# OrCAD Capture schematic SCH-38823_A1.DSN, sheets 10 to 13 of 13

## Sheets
10 Page10 WIFI&Bluetooth: size B
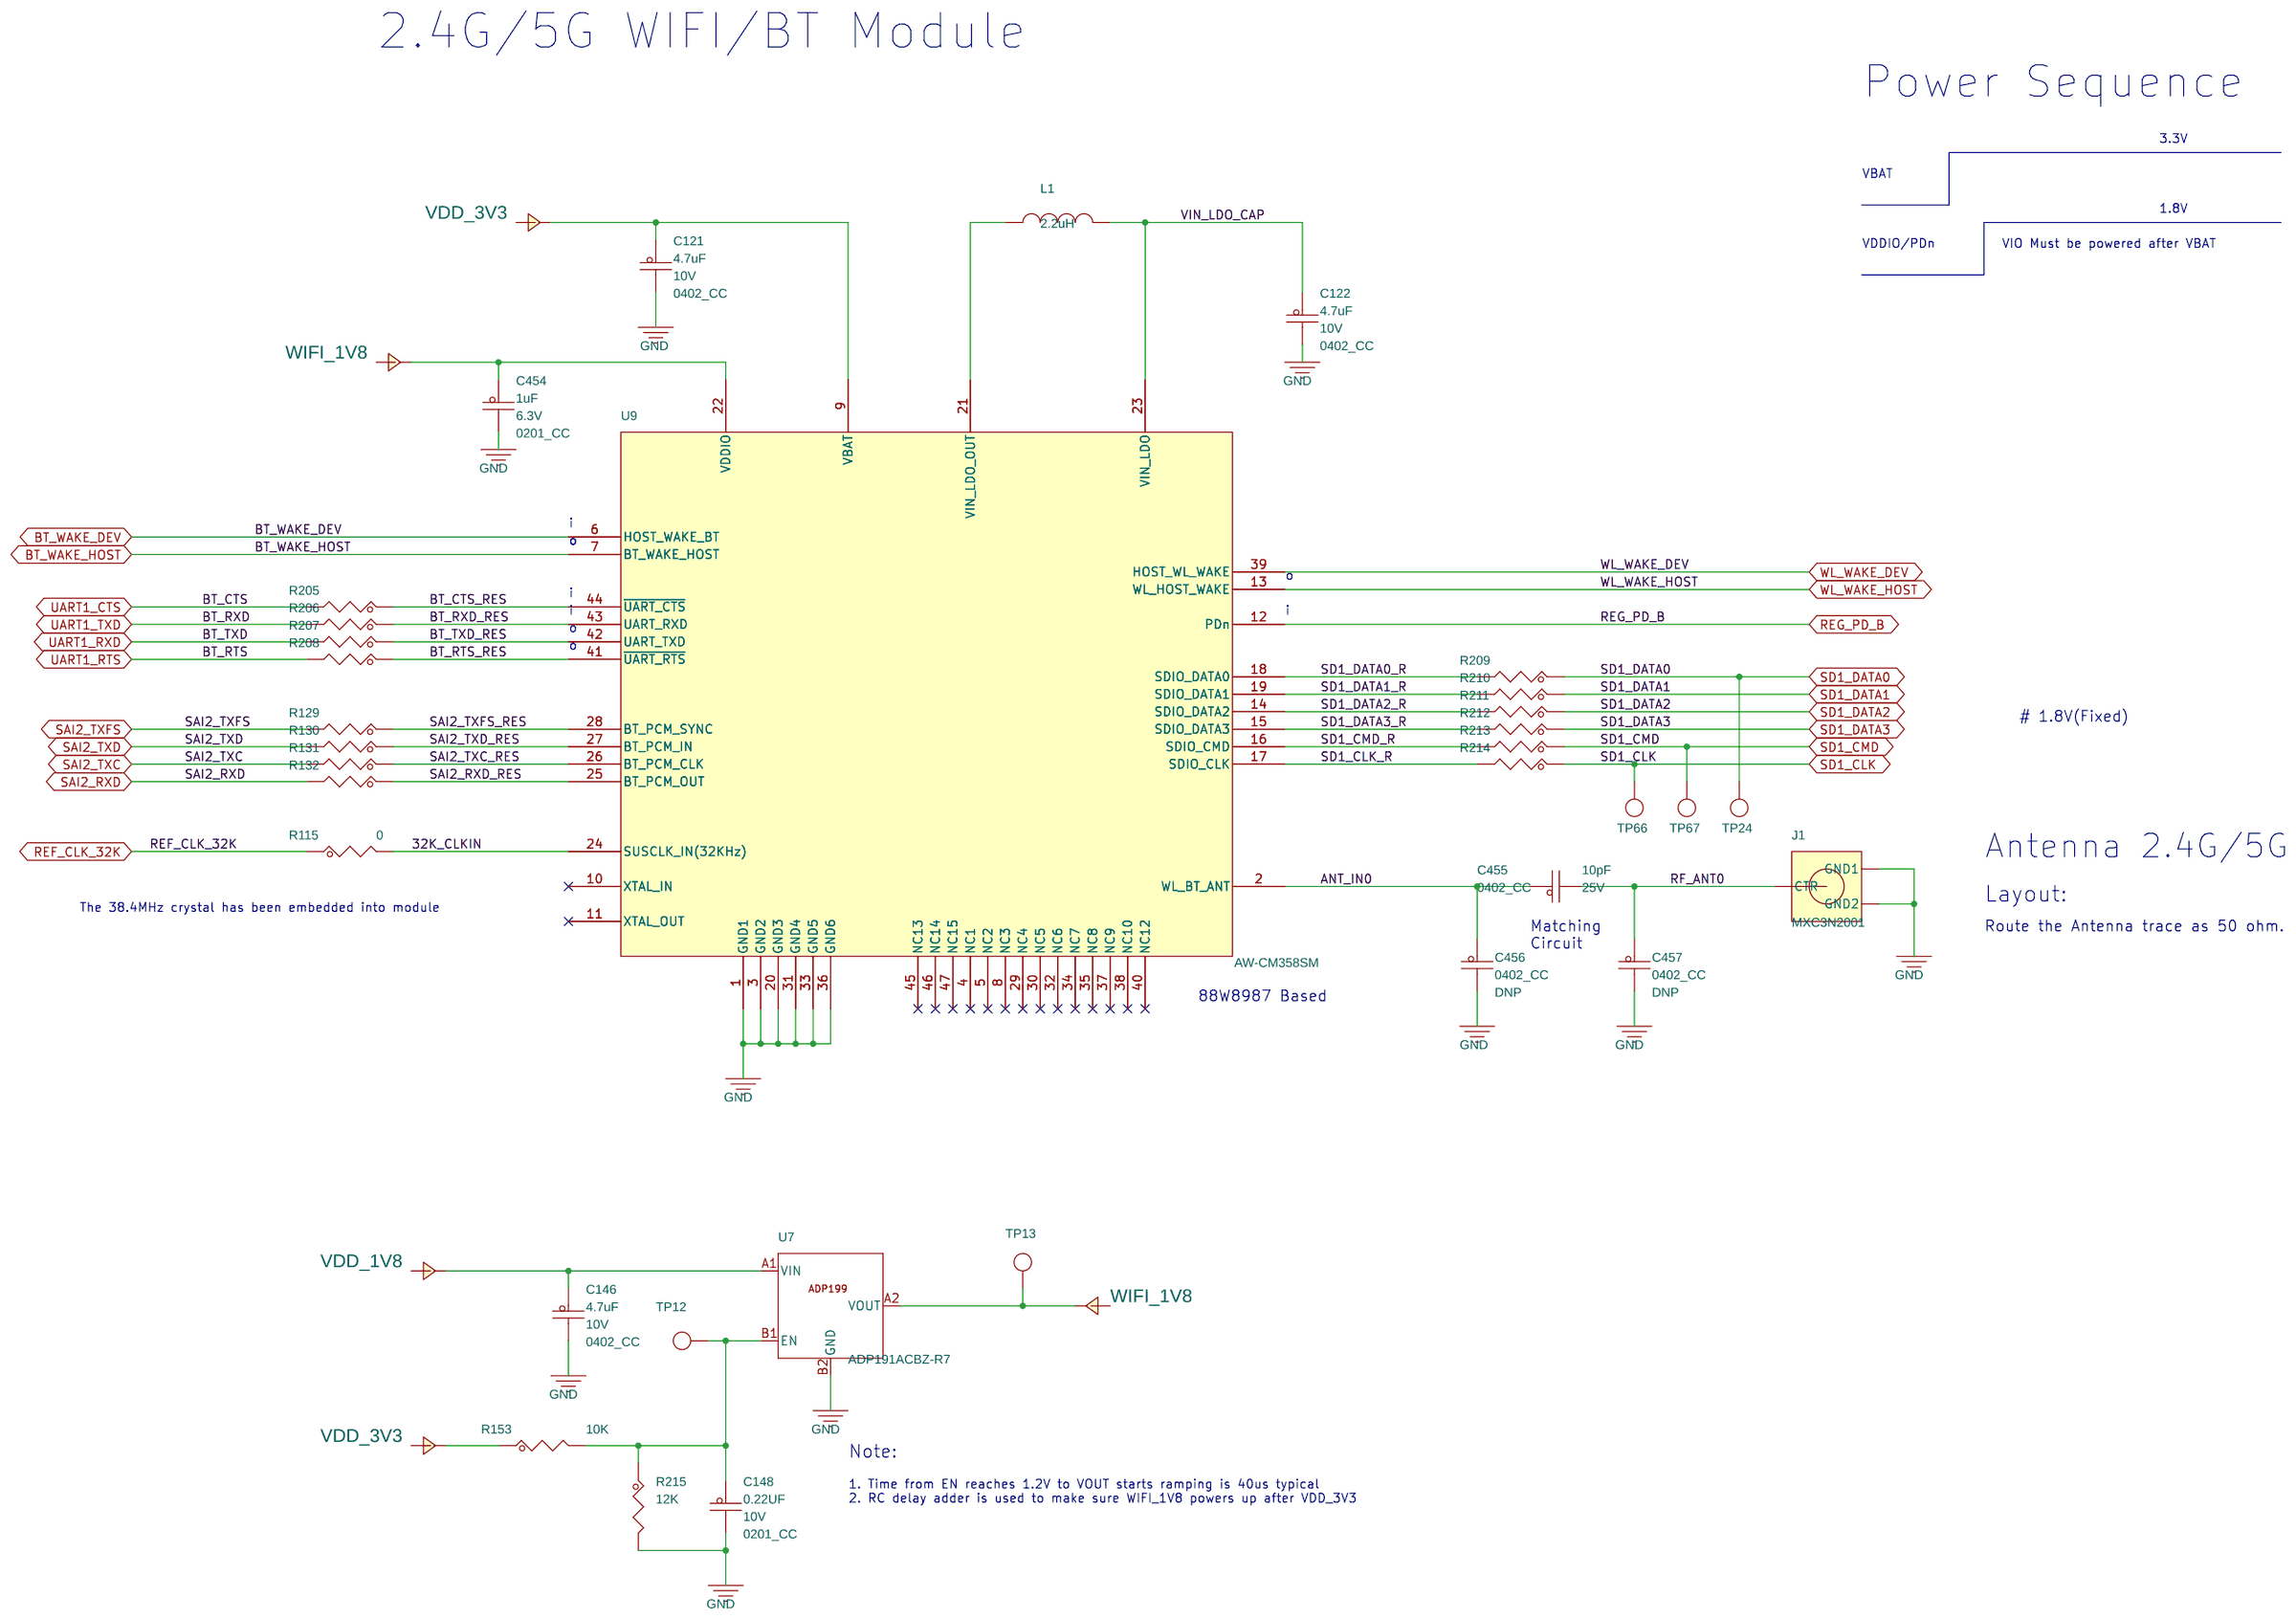
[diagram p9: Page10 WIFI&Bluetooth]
11 Page13 SOM Interface: size B; title: X-8MNANODLPD4-CPU
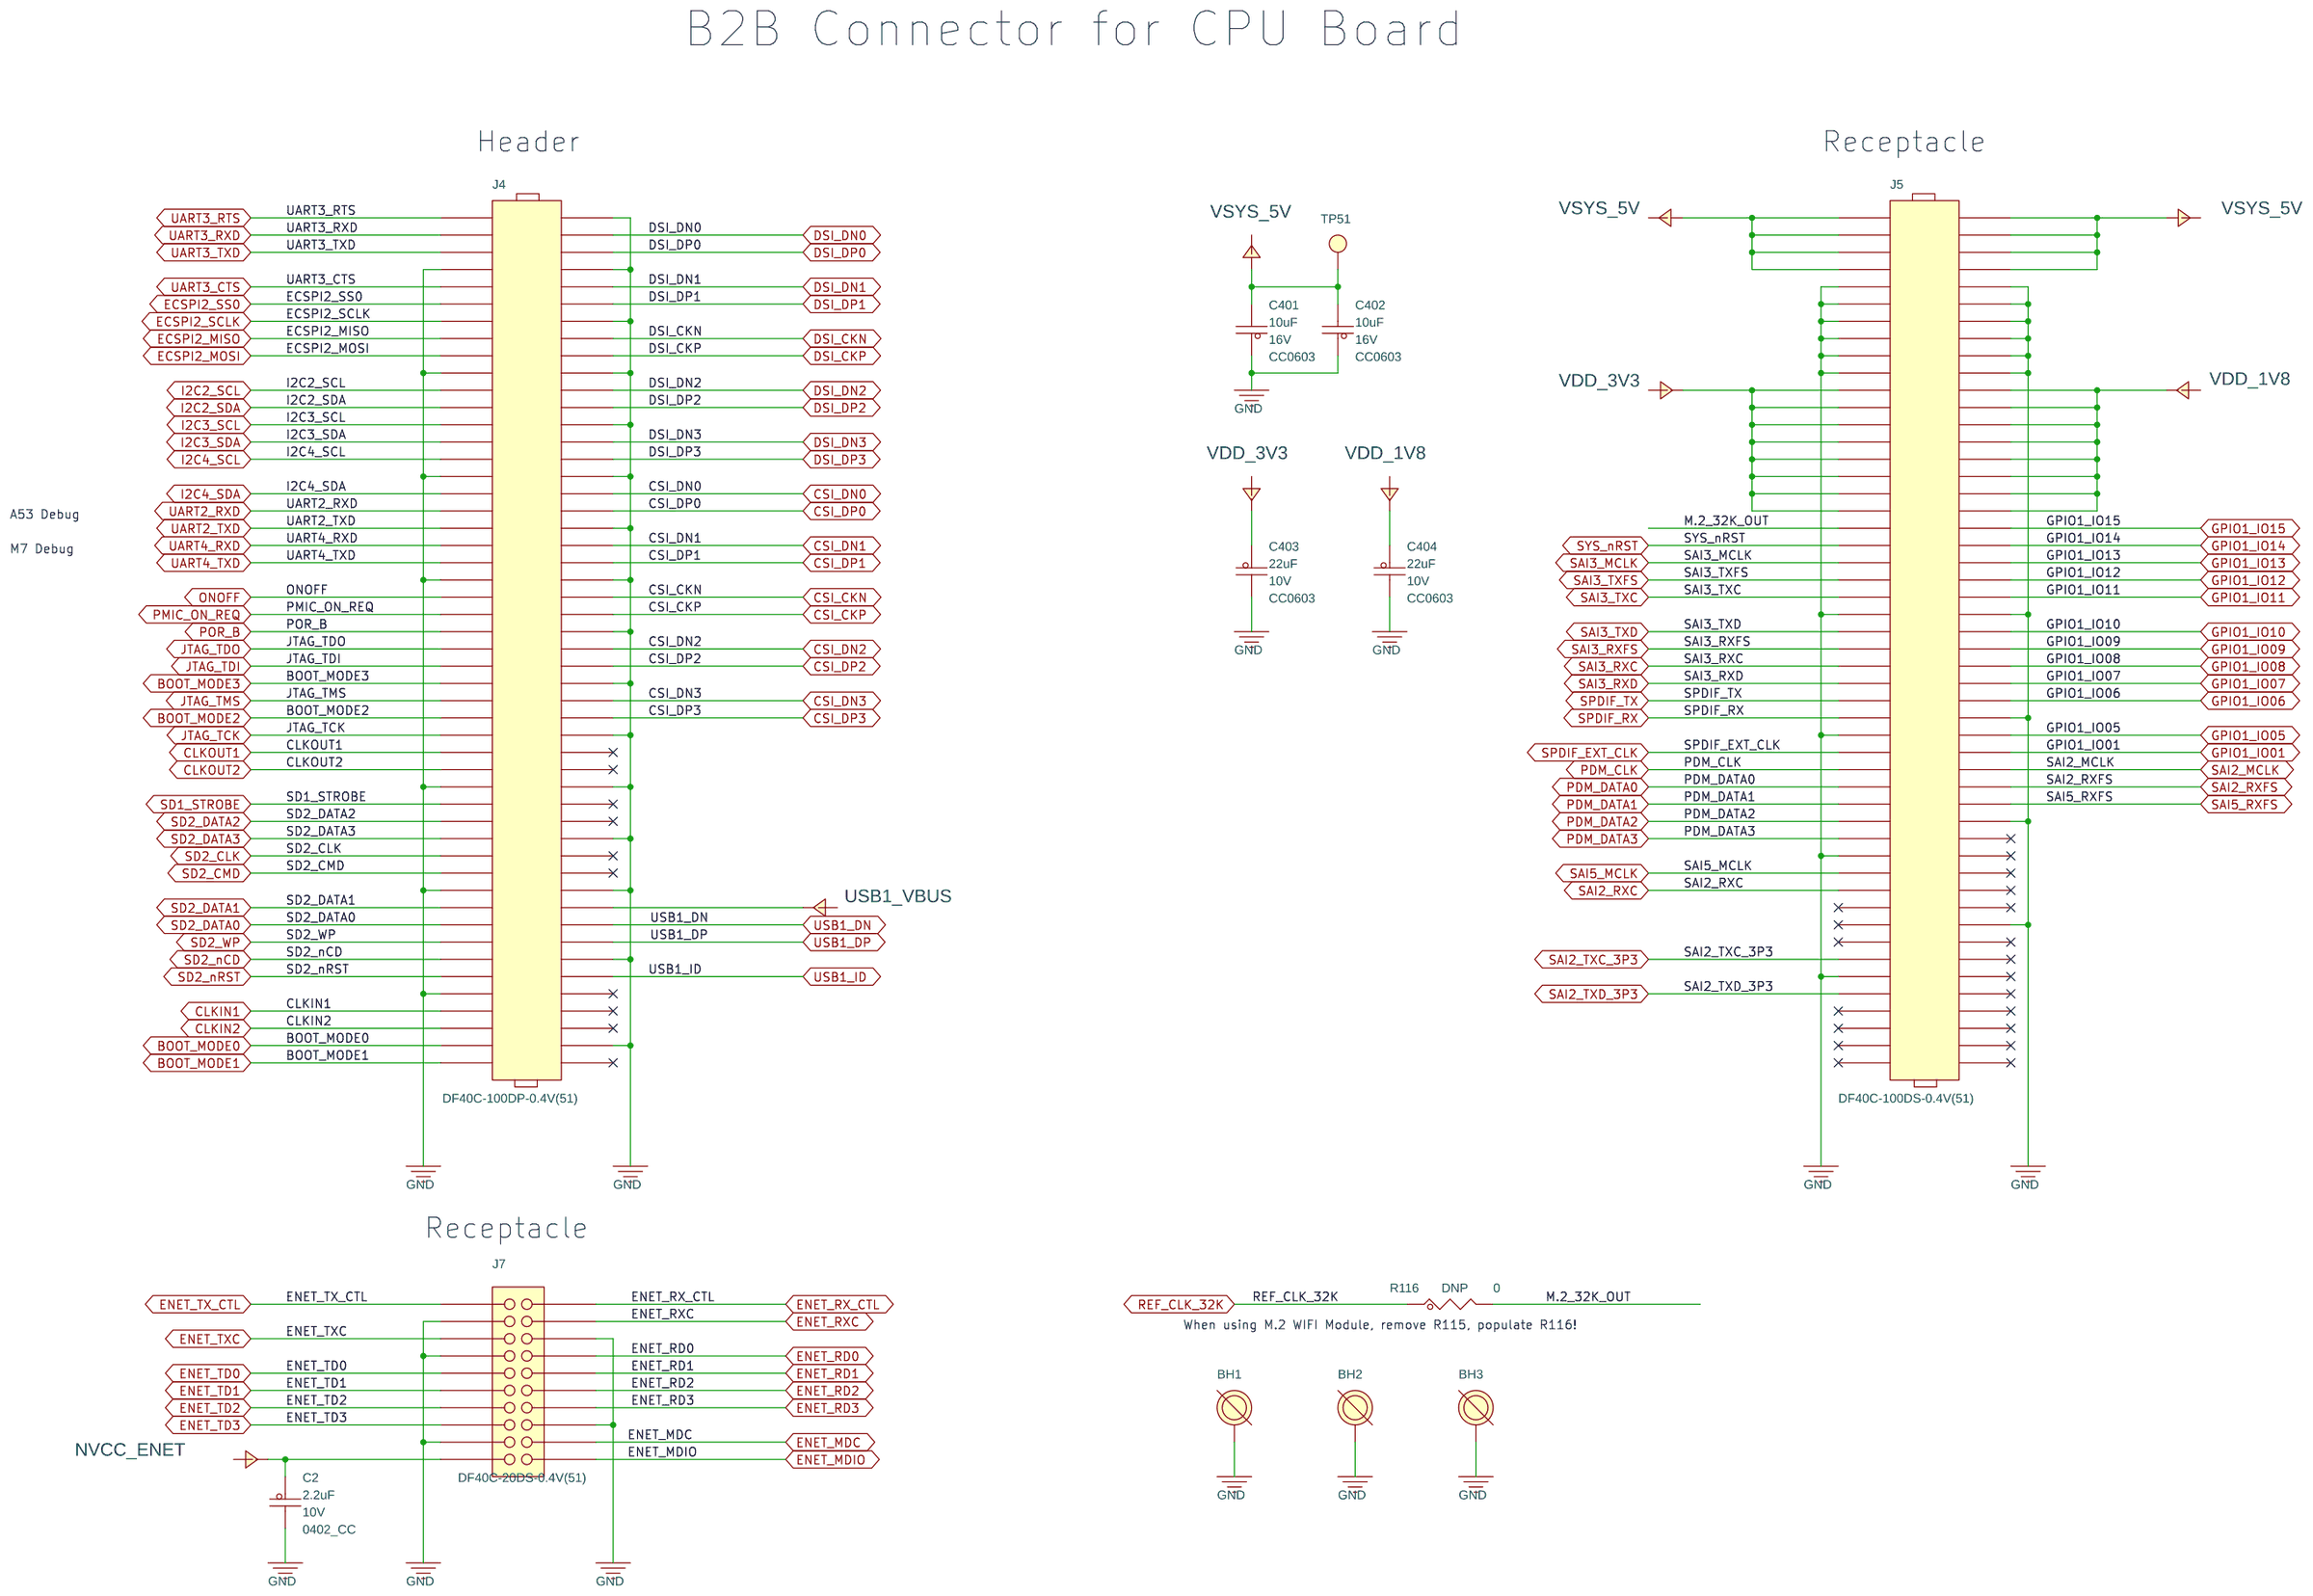
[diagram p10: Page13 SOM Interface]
12 Page12 PMIC PCA9450B: size C
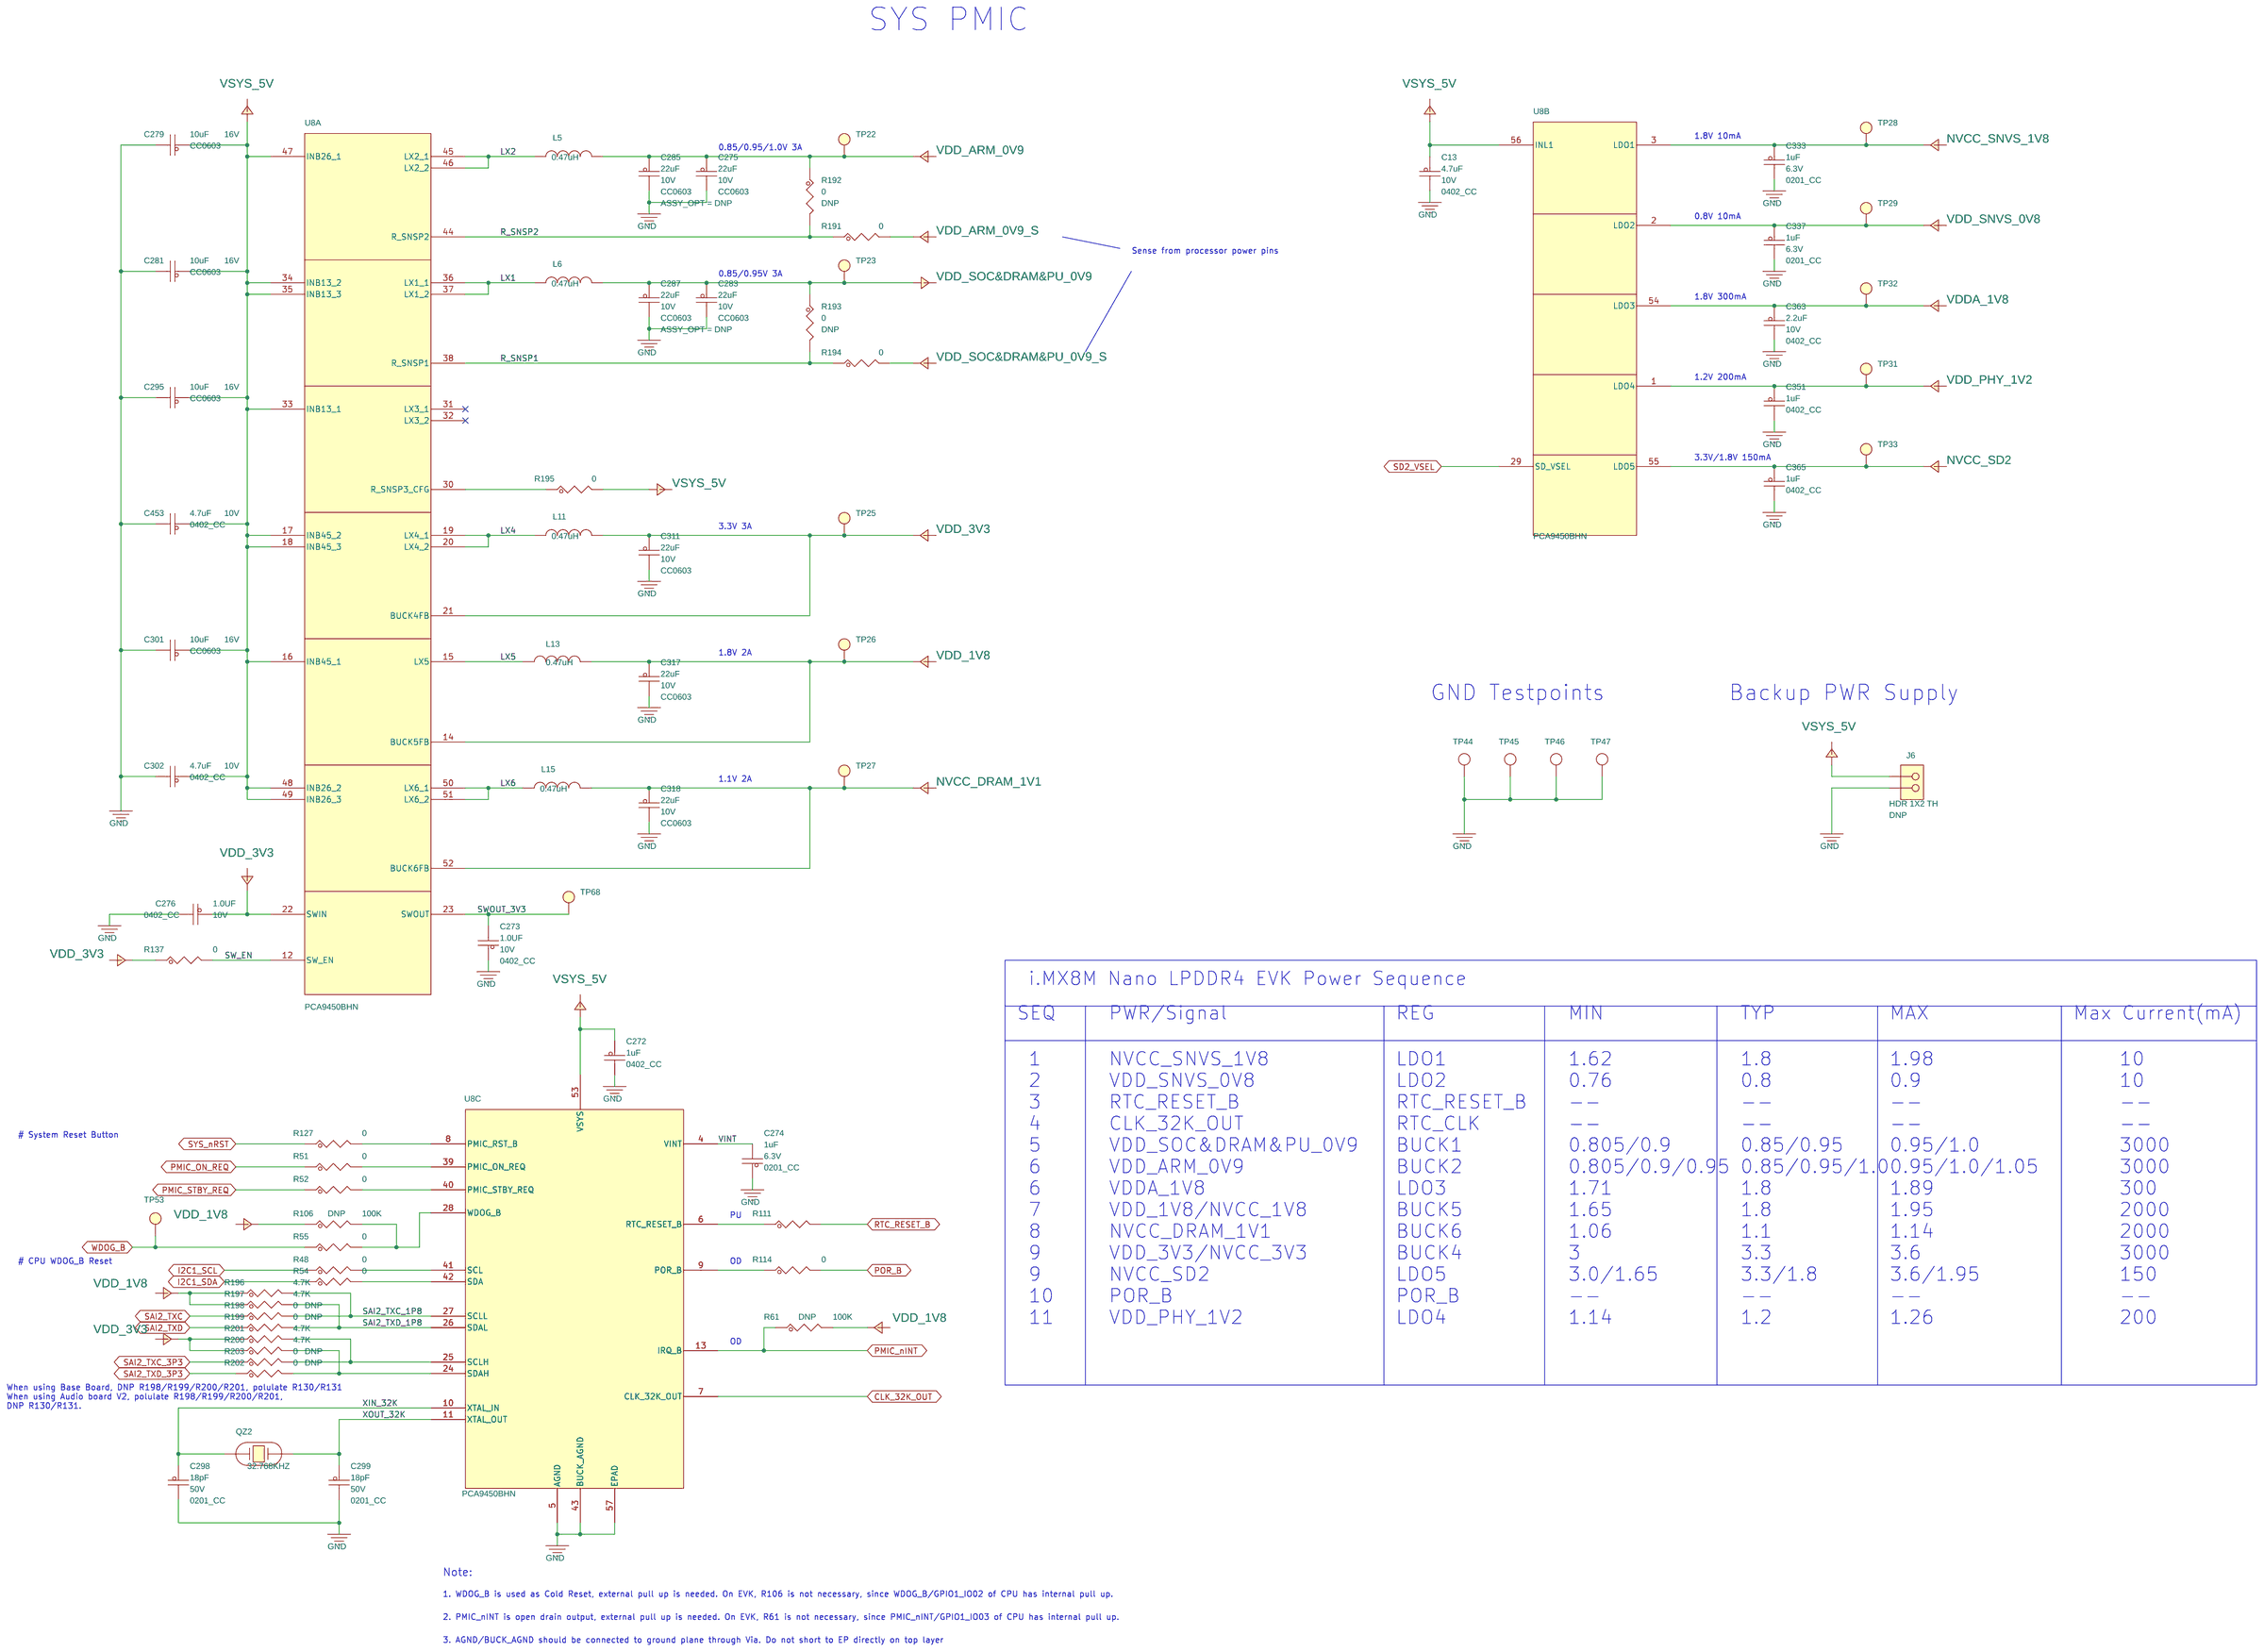
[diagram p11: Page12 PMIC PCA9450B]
13 Page09 eMMC/QSPI: size B
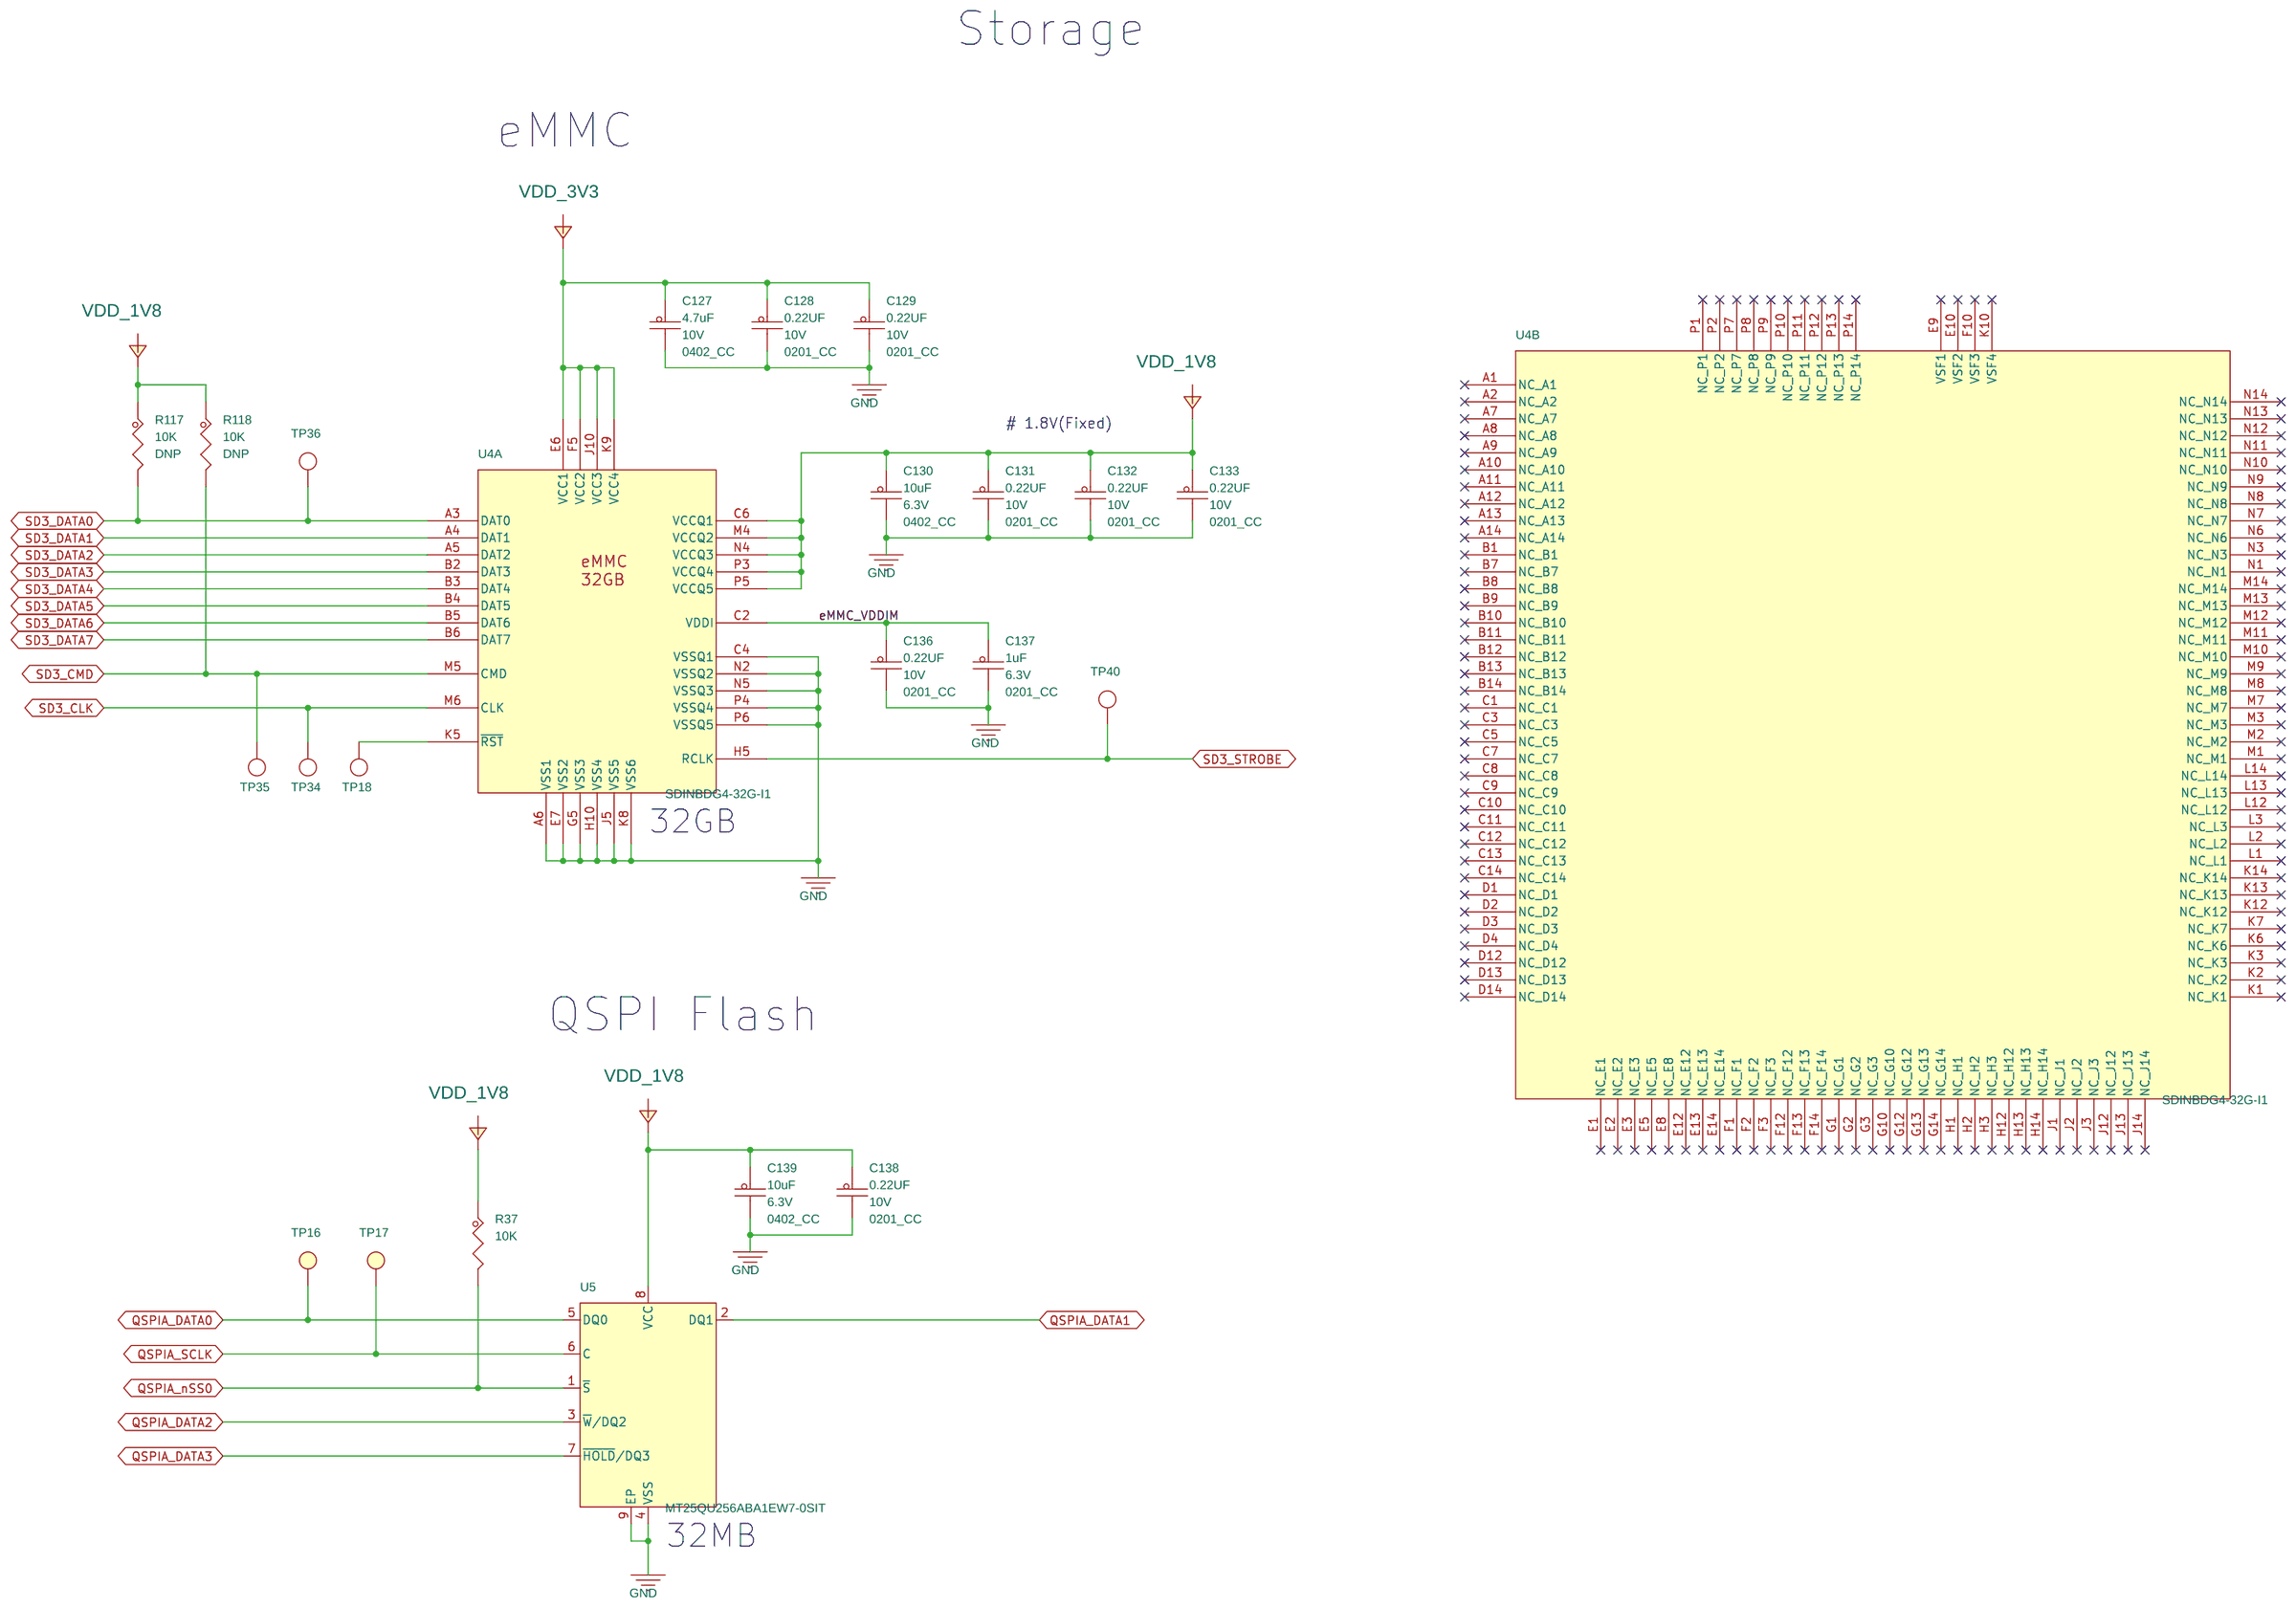
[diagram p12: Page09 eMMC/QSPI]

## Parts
sheet Page09 eMMC/QSPI
C127  4.7uF  [0402_CC]
C128  0.22UF  [0201_CC]
C129  0.22UF  [0201_CC]
C130  10uF  [0402_CC]
C131  0.22UF  [0201_CC]
C132  0.22UF  [0201_CC]
C133  0.22UF  [0201_CC]
C136  0.22UF  [0201_CC]
C137  1uF  [0201_CC]
C138  0.22UF  [0201_CC]
C139  10uF  [0402_CC]
R37  10K  [0402_CC]
R117  10K  [0201_CC]
R118  10K  [0201_CC]
TP16  TP_35MIL  [testpoint_35mil]
TP17  TP_35MIL  [testpoint_35mil]
TP18  TPAD_020  [tpad_020]
TP34  TPAD_020  [tpad_020]
TP35  TPAD_015  [TPAD_015]
TP36  TPAD_020  [tpad_020]
TP40  TPAD_015  [TPAD_015]
U4  SDINBDG4-32G-I1  [fbga153_0p5_11p5x13]  (sections A,B)
U5  MT25QU256ABA1EW7-0SIT  [dfn8_1p27_6x5mm_3p1]
sheet Page10 WIFI&Bluetooth
C121  4.7uF  [0402_CC]
C122  4.7uF  [0402_CC]
C146  4.7uF  [0402_CC]
C148  0.22UF  [0201_CC]
C454  1uF  [0201_CC]
C455  10pF  [0402_CC]
C456  10pF  [0402_CC]
C457  10pF  [0402_CC]
J1  MXC3N2001  [CON_3_UFL_R_SMT]
L1  2.2uH  [IND_0603A]
R115  0  [0402_CC]
R129  0  [0402_CC]
R130  0  [0402_CC]
R131  0  [0402_CC]
R132  0  [0402_CC]
R153  10K  [0201_CC]
R205  0  [0402_CC]
R206  0  [0402_CC]
R207  0  [0402_CC]
R208  0  [0402_CC]
R209  0  [0402_CC]
R210  0  [0402_CC]
R211  0  [0402_CC]
R212  0  [0402_CC]
R213  0  [0402_CC]
R214  0  [0402_CC]
R215  12K  [0201_CC]
TP12  TPAD_020  [tpad_020]
TP13  TPAD_020  [tpad_020]
TP24  TPAD_015  [TPAD_015]
TP66  TPAD_015  [TPAD_015]
TP67  TPAD_015  [TPAD_015]
U7  ADP191ACBZ-R7  [wlcsp4_0p4_0p8x0p8_smdp]
U9  AW-CM358SM  [module_wifi_0p9_12x12_47pin_a]
sheet Page12 PMIC PCA9450B
C13  4.7uF  [0402_CC]
C272  1uF  [0402_CC]
C273  1.0UF  [0402_CC]
C274  1uF  [0201_CC]
C275  22uF  [CC0603]
C276  1.0UF  [0402_CC]
C279  10uF  [CC0603]
C281  10uF  [CC0603]
C283  22uF  [CC0603]
C285  22uF  [CC0603]
C287  22uF  [CC0603]
C295  10uF  [CC0603]
C298  18pF  [0201_CC]
C299  18pF  [0201_CC]
C301  10uF  [CC0603]
C302  4.7uF  [0402_CC]
C311  22uF  [CC0603]
C317  22uF  [CC0603]
C318  22uF  [CC0603]
C333  1uF  [0201_CC]
C337  1uF  [0201_CC]
C351  1uF  [0402_CC]
C363  2.2uF  [0402_CC]
C365  1uF  [0402_CC]
C453  4.7uF  [0402_CC]
J6  HDR 1X2 TH  [HDR_1X2]
L5  0.47uH  [ind_sph2520]
L6  0.47uH  [ind_sph2520]
L11  0.47uH  [ind_sph2520]
L13  0.47uH  [IND_2016A]
L15  0.47uH  [ind_sph2520]
QZ2  32.768KHZ  [XTAL2-3P2X1P5-SM]
R48  0  [0402_CC]
R51  0  [0402_CC]
R52  0  [0402_CC]
R54  0  [0402_CC]
R55  0  [0402_CC]
R61  100K  [0201_CC]
R106  100K  [0201_CC]
R111  0  [0402_CC]
R114  0  [0402_CC]
R127  0  [0402_CC]
R137  0  [0402_CC]
R191  0  [0402_CC]
R192  0  [0402_CC]
R193  0  [0402_CC]
R194  0  [0402_CC]
R195  0  [0402_CC]
R196  4.7K  [0201_CC]
R197  4.7K  [0201_CC]
R198  0  [0402_CC]
R199  0  [0402_CC]
R200  4.7K  [0201_CC]
R201  4.7K  [0201_CC]
R202  0  [0402_CC]
R203  0  [0402_CC]
TP22  TP_35MIL  [testpoint_35mil]
TP23  TP_35MIL  [testpoint_35mil]
TP25  TP_35MIL  [testpoint_35mil]
TP26  TP_35MIL  [testpoint_35mil]
TP27  TP_35MIL  [testpoint_35mil]
TP28  TP_35MIL  [testpoint_35mil]
TP29  TP_35MIL  [testpoint_35mil]
TP31  TP_35MIL  [testpoint_35mil]
TP32  TP_35MIL  [testpoint_35mil]
TP33  TP_35MIL  [testpoint_35mil]
TP44  TPAD_050  [TPAD_050]
TP45  TPAD_050  [TPAD_050]
TP46  TPAD_050  [TPAD_050]
TP47  TPAD_050  [TPAD_050]
TP53  TP_35MIL  [testpoint_35mil]
TP68  TP_35MIL  [testpoint_35mil]
U8  PCA9450BHN  [hvqfn56_0p4_7x7_ep4p7mm]  (sections A,B,C)
sheet Page13 SOM Interface
BH1  MOUNTING HOLE  [GNDPOINT256]
BH2  MOUNTING HOLE  [GNDPOINT256]
BH3  MOUNTING HOLE  [GNDPOINT256]
C2  2.2uF  [0402_CC]
C401  10uF  [CC0603]
C402  10uF  [CC0603]
C403  22uF  [CC0603]
C404  22uF  [CC0603]
J4  DF40C-100DP-0.4V(51)  [con100_0p4_21p7x2p05_sm]
J5  DF40C-100DS-0.4V(51)  [con100_0p4_22p8x3p1_sm]
J7  DF40C-20DS-0.4V(51)  [con20_0p4_6p8x3p1_sm]
R116  0  [0402_CC]
TP51  TP_35MIL  [testpoint_35mil]

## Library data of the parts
C13 C121 C122 C127 C146 C302 C453 = CAP_NP: CAP CER 4.7uF 10V 10% X5R 0402; AGILE_PN: 150-80044; CAD_APPROVED: Yes; FPLIST: CC0402_25,CC0402_HD,0402_CC; HEIGHT: 0.65MM; MFG_NAME01: Samsung Electro Mechanics; MFG_PN01: CL05A475KP5NRNC; ROHS: Yes; Tolerance: 10%; VOLTAGE: 10V
C128 C129 C131-C133 C136 C138 C148 = CAP_NP: CAP CER 0.22UF 10V 20% X5R 0201; AGILE_PN: 150-78815; CAD_APPROVED: Yes; FPLIST: CC0201,CC0201_HD,0201_CC; HEIGHT: 0.33MM; MFG_NAME01: Taiyo Yuden; MFG_PN01: LMK063BJ224MP-F; ROHS: Yes; Tolerance: 20%; VOLTAGE: 10V
C130 C139 = CAP_NP: CAP CER 10UF 6.3V 20% X5R 0402; AGILE_PN: 150-79163; CAD_APPROVED: Yes; FPLIST: CC0402_25,CC0402_HD,0402_CC; HEIGHT: 0.65 MM; MFG_NAME01: SAMSUNG ELECTRO MECHANICS; MFG_PN01: CL05A106MQ5NUNC; ROHS: Yes; Tolerance: 20%; VOLTAGE: 6.3V
C137 C274 C333 C337 C454 = CAP_NP: CAP CER 1uF 6.3V 20% X5R 0201; AGILE_PN: 150-79407; CAD_APPROVED: Yes; FPLIST: CC0201,CC0201_HD,0201_CC,0201_CC_012SM_NSP; HEIGHT: 0.35MM; MFG_NAME01: AVX; MFG_PN01: 02016D105MAT2A; Package Size: 0201; Package Type: 7” reel; ROHS: Yes; Tolerance: 20%; VOLTAGE: 6.3V
R37 = RES: RES MF 10K 1/16W 5% 0402; AGILE_PN: 470-75557; CAD_APPROVED: Yes; FPLIST: RC0402_25,RC0402_HD,0402_CC; HEIGHT: 0.4 MM; MFG_NAME01: VISHAY INTERTECHNOLOGY; MFG_PN01: CRCW040210K0JNED; ROHS: Yes; Tolerance: 5%
R117 R118 = RES: RES MF 10K 1/20W 5% 0201; AGILE_PN: 470-79719; ASSY_OPT: DNP; CAD_APPROVED: Yes; FPLIST: RC0201,0201_CC; HEIGHT: 0.26 MM; MFG_NAME01: RALEC ELECTRONIC CORP; MFG_PN01: RTT01103JTH; ROHS: Yes; Tolerance: 5%
TP16 TP17 TP22 TP23 TP25-TP29 TP31-TP33 TP51 TP53 TP68 = T_POINT_R: TEST POINT PAD .035 SMT, no part to order; AGILE_PN: 510-75618; ASSY_OPT: DNP; CAD_APPROVED: Yes; HEIGHT: 0.1MM; ROHS: Yes
TP18 TP34 TP36 = TESTLOOP: TEST POINT PAD 0.5MM DIA SMT, NO PART TO ORDER; AGILE_PN: 211-77484; ASSY_OPT: DNP; CAD_APPROVED: Yes; HEIGHT: 0.1MM; ROHS: Yes
TP24 TP35 TP66 TP67 = TESTLOOP: TEST POINT PAD 15MIL DIA SMT, NO PART TO ORDER; AGILE_PN: 211-76645; ASSY_OPT: DNP; CAD_APPROVED: Yes; HEIGHT: 0.1MM; MFG_NAME01: NOTACOMPONENT; MFG_PN01: NOTACOMPONENT; ROHS: Yes
TP40 = TESTLOOP: TEST POINT PAD 15MIL DIA SMT, NO PART TO ORDER; AGILE_PN: 211-76645; CAD_APPROVED: Yes; HEIGHT: 0.1MM; MFG_NAME01: NOTACOMPONENT; MFG_PN01: NOTACOMPONENT; ROHS: Yes
U4 = SDINBDG4-16G_VFBGA_153P: IC MEM NAND FLASH 32GB eMMC 5.1 CTLR 2.7-3.6V FBGA153; AGILE_PN: 342-00840; HEIGHT: 1MM; MFG_NAME01: SanDisk; Package Size: 11.5 mm x 13 mm x 1 mm; ROHS: YES; Supply Voltage: 2.7 V to 3.6 V; Temp Range: -25°C to +85°C; VOLTAGE: 2.7-3.6V
U5 = MT25QL256ABA1EW9_9P: IC MEM FLASH SERIAL NOR 256MBIT 166MHZ 1.7-2V WPDFN8; AGILE_PN: 334-77688; CAD_APPROVED: Yes; HEIGHT: 0.8 MM; MFG_NAME01: MICRON; ROHS: Yes; VOLTAGE: 1.7-2V
C455 = CAP_NP: CAP CER 10PF 25V 5% C0G 0402; AGILE_PN: 150-30134; CAD_APPROVED: Yes; FPLIST: CC0402_25,CC0402_HD,0402_CC; HEIGHT: 0.635 MM; MFG_NAME01: VENKEL COMPANY; MFG_PN01: C0402C0G250-100JNP; Package Size: Paper Tape (7" Reel); Package Type: 0402; ROHS: Yes; Tolerance: 5%; VOLTAGE: 25V
C456 C457 = CAP_NP: CAP CER 10PF 25V 5% C0G 0402; AGILE_PN: 150-30134; ASSY_OPT: DNP; CAD_APPROVED: Yes; FPLIST: CC0402_25,CC0402_HD,0402_CC; HEIGHT: 0.635 MM; MFG_NAME01: VENKEL COMPANY; MFG_PN01: C0402C0G250-100JNP; Package Size: Paper Tape (7" Reel); Package Type: 0402; ROHS: Yes; Tolerance: 5%; VOLTAGE: 25V
J1 = UFL: CON 1 COAX SKT SMT 55H AU; AGILE_PN: 211-79898; CAD_APPROVED: Yes; HEIGHT: 1.4MM; MFG_NAME01: SHENZHEN ATOM TECHNOLOGY CO.,LTD; ROHS: Yes
L1 = INDUCTOR: IND -- 2.2UH@1MHZ 1.05A 20% 0603; AGILE_PN: 180-78587; CAD_APPROVED: Yes; FPLIST: IND_0603A,0603_CC; HEIGHT: 1MM; MFG_NAME01: MURATA; MFG_PN01: LQM18PN2R2MGH; ROHS: Yes; Temp Range: -40C to + 85C; Temp_Range: -40C to + 85C; Tolerance: 20%
R51 R114 R115 R137 = RES: RES MF ZERO OHM 1/16W 5% 0402; AGILE_PN: 470-75394; CAD_APPROVED: Yes; HEIGHT: 0.45 MM; MFG_NAME01: YAGEO AMERICA; MFG_PN01: RC0402JR-070RL; ROHS: Yes; Tolerance: 5%; VOLTAGE: 1/16W
R129-R132 R205-R214 = RES: RES MF ZERO OHM 1/16W 5% 0402; AGILE_PN: 470-75394; CAD_APPROVED: Yes; FPLIST: RC0402_25,RC0402_HD,RC0402_X2,0402_CC; HEIGHT: 0.45 MM; MFG_NAME01: YAGEO AMERICA; MFG_PN01: RC0402JR-070RL; ROHS: Yes; SIGNAL_MODEL: DEFAULT_RESISTOR_10000OHM_2_1; TOL: 1%; Tolerance: 5%; VOLTAGE: 1/16W
R153 = RES: RES MF 10K 1/20W 5% 0201; AGILE_PN: 470-79719; CAD_APPROVED: Yes; FPLIST: RC0201,0201_CC; HEIGHT: 0.26 MM; MFG_NAME01: RALEC ELECTRONIC CORP; MFG_PN01: RTT01103JTH; ROHS: Yes; Tolerance: 5%
R215 = RES: RES MF 12K 1/20W 1% 0201; AGILE_PN: 470-77701; CAD_APPROVED: Yes; FPLIST: RC0201,0201_CC; HEIGHT: 0.26MM; MFG_NAME01: SKYMOS; MFG_PN01: RC-0201-123FT; ROHS: Yes; Tolerance: 1%; VOLTAGE: 1/20W
TP12 TP13 = TESTLOOP: TEST POINT PAD 0.5MM DIA SMT, NO PART TO ORDER; AGILE_PN: 211-77484; CAD_APPROVED: Yes; HEIGHT: 0.1MM; ROHS: Yes
U7 = ADP199_4P: IC HIGH SIDE PWR SW 1.1-3.6V WLCSP4; AGILE_PN: 315-82028; CAD_APPROVED: Yes; HEIGHT: 0.66MM; MFG_NAME01: ANALOG DEVICES; ROHS: Yes; Temp Range: -45 to 85 C; Temp_Range: -45 to 85 C; VOLTAGE: 1.1-3.6V
U9 = AW_CM358SM: IC XCVR WIFI BLUETOOTH MODULE 802.11A/B/G/N/AC 3.07-3.53V SMD; AGILE_PN: 312-82329; CAD_APPROVED: Yes; HEIGHT: 1.9MM; MFG_NAME01: Azurewave Technologies, Inc.; ROHS: Yes; Temp Range: -30°C to +85°C; VOLTAGE: 3.07-3.53V
C272 C351 C365 = CAP_NP: CAP CER 1uF 10V 10% X7S 0402; AGILE_PN: 150-80357; CAD_APPROVED: Yes; FPLIST: CC0402_25,CC0402_HD,0402_CC; HEIGHT: 0.6MM; MFG_NAME01: MURATA; MFG_PN01: GRM155C71A105KE11D; Package Size: 0402; ROHS: Yes; Temp Range: -55C - 125C; Temp_Range: -55C - 125C; Tolerance: 10%; VOLTAGE: 10
C273 C276 = CAP_NP: CAP CER 1.0UF 10V 10% X5R 0402; AGILE_PN: 150-75772; CAD_APPROVED: Yes; FPLIST: CC0402_25,CC0402_HD,0402_CC; HEIGHT: 0.6MM; MFG_NAME01: YAGEO AMERICA; MFG_PN01: CC0402KRX5R6BB105; Package Size: 0402; ROHS: Yes; VOLTAGE: 10V
C275 C283 C311 C317 C318 C403 C404 = CAP_NP: CAP CER 22uF 10V 20% X5R 0603; AGILE_PN: 150-79530; CAD_APPROVED: Yes; FPLIST: CC0603_OV,CC0603,0603_CC; HEIGHT: 1MM; MFG_NAME01: TDK; MFG_PN01: C1608X5R1A226M080AC; Package Size: 0603; ROHS: Yes; SIGNAL_MODEL: DEFAULT_CAPACITOR_2.2e+07pF_2_1; Tolerance: 20%; VOLTAGE: 10V; WVDC: 6.3V
C279 C281 C295 C301 C401 C402 = CAP_NP: CAP CER 10.0uF 16V 10% X5R 0603; AGILE_PN: 150-80060; CAD_APPROVED: Yes; FPLIST: CC0603_OV,CC0603,0603_CC,cc0603_0805_nsp; HEIGHT: 0.9MM; MFG_NAME01: MURATA; MFG_PN01: GRM188R61C106KAALD; Package Size: 0603; Package Type: SMT; ROHS: Yes; Temp Range: -55°C to +85°C; Temp_Range: -55°C to +85°C; Tolerance: 10%; VOLTAGE: 16V
C285 C287 = CAP_NP: CAP CER 22uF 10V 20% X5R 0603; AGILE_PN: 150-79530; ASSY_OPT: DNP; CAD_APPROVED: Yes; FPLIST: CC0603_OV,CC0603,0603_CC; HEIGHT: 1MM; MFG_NAME01: TDK; MFG_PN01: C1608X5R1A226M080AC; Package Size: 0603; ROHS: Yes; SIGNAL_MODEL: DEFAULT_CAPACITOR_2.2e+07pF_2_1; Tolerance: 20%; VOLTAGE: 10V; WVDC: 6.3V
C298 C299 = CAP_NP: CAP CER 18pF 50V 5% C0G 0201; AGILE_PN: 150-79476; CAD_APPROVED: Yes; FPLIST: CC0201,CC0201_HD,0201_CC; HEIGHT: 0.33MM; MFG_NAME01: MURATA; MFG_PN01: GRM0335C1H180JA01D; Package Size: 0201; Package Type: &#966;180mm Paper taping; ROHS: Yes; Tolerance: 5%; VOLTAGE: 50V
C2 C363 = CAP_NP: CAP CER 2.2uF 10V 10% X5R 0402; AGILE_PN: 150-78974; CAD_APPROVED: Yes; FPLIST: CC0402_25,CC0402_HD,0402_CC; HEIGHT: 0.55 MM; MFG_NAME01: TDK; MFG_PN01: C1005X5R1A225K; Package Size: 0402; ROHS: Yes; Tolerance: 10%; VOLTAGE: 10V
J6 = CONN_HDR_2X1: HDR 1X2 TH 100MIL SP 339H AU 98L; AGILE_PN: 210-75439; ASSY_OPT: DNP; CAD_APPROVED: YES; FPLIST: HDR102,SH_HDR102_BOTTOM; HEIGHT: 8.71 MM; MFG_NAME01: SAMTEC; MFG_PN01: TSW-102-07-G-S; ROHS: Yes; Temp Range: -55°C to +125°C; Temp_Range: -55°C to +125°C
L5 L6 L11 L15 = INDUCTOR: IND PWR 0.47uH@1MHZ 4.7A 20% SMT; AGILE_PN: 180-78647; CAD_APPROVED: Yes; HEIGHT: 1.2MM; MFG_NAME01: SHENZHEN SUNLORD ELECTRONICS CO., LTD; MFG_PN01: WPN252012ER47MT; PART_TYPE: INDUCTOR\POWER; ROHS: Yes; TOL: 20%; Temp Range: -40°C to +125°C; Temp_Range: -40°C to +125°C; Tolerance: 20%
L13 = INDUCTOR: IND WW 0.47uH@1MHz 3.4A 20% 2016; AGILE_PN: 180-78630; CAD_APPROVED: Yes; HEIGHT: 1.2MM; MFG_NAME01: MURATA; MFG_PN01: 1286AS-H-R47M=P2; ROHS: Yes; Temp Range: -40C to +85C; Temp_Range: -40C to +85C; Tolerance: 20%; VOLTAGE: 20V DC
QZ2 = XTAL: XTAL 32.768KHZ 12.5PF 20PPM 3.2X1.5MM SMT; AGILE_PN: 230-77653; CAD_APPROVED: Yes; HEIGHT: 0.9MM; MFG_NAME01: Abracon Corporation; MFG_PN01: ABS07-32.768KHZ-T; ROHS: Yes
R48 R52 R54 R55 R127 R191 R194 R195 = RES: RES MF ZERO OHM 1/16W 5% 0402; AGILE_PN: 470-75394; CAD_APPROVED: Yes; FPLIST: RC0402_25,RC0402_HD,RC0402_X2,0402_CC; HEIGHT: 0.45 MM; MFG_NAME01: YAGEO AMERICA; MFG_PN01: RC0402JR-070RL; ROHS: Yes; Tolerance: 5%; VOLTAGE: 1/16W
R61 R106 = RES: RES MF 100K 1/20W 1% 0201; AGILE_PN: 470-77704; ASSY_OPT: DNP; CAD_APPROVED: Yes; FPLIST: RC0201,0201_CC; HEIGHT: 0.26MM; MFG_NAME01: SKYMOS; MFG_PN01: RC-0201-104FT; ROHS: Yes; Tolerance: 1%
R111 = RES: RES MF ZERO OHM 1/16W 5% 0402; AGILE_PN: 470-75394; CAD_APPROVED: Yes; HEIGHT: 0.45 MM; MFG_NAME01: YAGEO AMERICA; MFG_PN01: RC0402JR-070RL; ROHS: Yes; SIGNAL_MODEL: DEFAULT_RESISTOR_10000OHM_2_1; TOL: 1%; Tolerance: 5%; VOLTAGE: 1/16W
R192 R193 R198 R199 R202 R203 = RES: RES MF ZERO OHM 1/16W 5% 0402; AGILE_PN: 470-75394; ASSY_OPT: DNP; CAD_APPROVED: Yes; FPLIST: RC0402_25,RC0402_HD,RC0402_X2,0402_CC; HEIGHT: 0.45 MM; MFG_NAME01: YAGEO AMERICA; MFG_PN01: RC0402JR-070RL; ROHS: Yes; Tolerance: 5%; VOLTAGE: 1/16W
R196 R197 R200 R201 = RES: RES MF 4.7K 1/20W 5% AEC-Q200 0201; AGILE_PN: 470-79700; CAD_APPROVED: Yes; FPLIST: RC0201,0201_CC; HEIGHT: 0.25MM; MFG_NAME01: KOA SPEER; MFG_PN01: RK73B1HTTC472J; ROHS: Yes; Temp Range: -55C to +155C; Temp_Range: -55C to +155C; Tolerance: 5%
TP44-TP47 = TESTLOOP: TEST POINT PAD 50MIL DIA SMT, NO PART TO ORDER; AGILE_PN: 211-76644; ASSY_OPT: DNP; CAD_APPROVED: Yes; HEIGHT: 0.1MM; MFG_NAME01: NOTACOMPONENT; MFG_PN01: NOTACOMPONENT; ROHS: Yes
U8 = PCA9450_HVQFN56P_A: IC POWER MANAGEMENT 2.7-5.5V HVQFN56; AGILE_PN: TMP-WF-36197; CAD_APPROVED: Yes; HEIGHT: 1MM; MFG_NAME01: NXP SEMICONDUCTORS; PRE_APN: 315-82314; ROHS: Yes; Temp Range: -40C to +105C; Temp_Range: -40C to +105C; VOLTAGE: 2.7-5.5V
BH1-BH3 = MOUNT_HOLE: MOUNTING HOLE DRILL 109 PAD 200 PLATED TH NO PART TO ORDER; AGILE_PN: 280-75147; ASSY_OPT: DNP; CAD_APPROVED: Yes; HEIGHT: 0.005 MILS; ROHS: Yes
J4 = HDR_2X50_M: CON 2X50 PLUG SHRD SMT 0.4MM SP 51H AU; AGILE_PN: 211-80305; CAD_APPROVED: Yes; HEIGHT: 1.29MM; MFG_NAME01: HIROSE; ROHS: Yes; Temp Range: -35 to 85 &#8451;; Temp_Range: -35 to 85 &#8451;
J5 = HDR_2X50_M: CON 2X50 SKT SHRD SMT 0.4MM SP 65H AU; AGILE_PN: 211-80183; CAD_APPROVED: Yes; HEIGHT: 1.65 MM; MFG_NAME01: HIROSE; Package Type: SMT; ROHS: Yes; Temp Range: -35C to +85C; Temp_Range: -35C to +85C
J7 = CONN_HDR_10X2: CON 2X10 SKT SHRD SMT 0.4MM SP 63H AU; AGILE_PN: 211-80328; CAD_APPROVED: Yes; HEIGHT: 1.6MM; MFG_NAME01: HIROSE; ROHS: Yes; Temp Range: -35C to 85C; Temp_Range: -35C to 85C
R116 = RES: RES MF ZERO OHM 1/16W 5% 0402; AGILE_PN: 470-75394; ASSY_OPT: DNP; CAD_APPROVED: Yes; HEIGHT: 0.45 MM; MFG_NAME01: YAGEO AMERICA; MFG_PN01: RC0402JR-070RL; ROHS: Yes; Tolerance: 5%; VOLTAGE: 1/16W

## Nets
GND: BH1.1 BH2.1 BH3.1 C2.2 C13.2 C121.2 C122.2 C127.2 C128.2 C129.2 C130.2 C131.2 C132.2 C133.2 C136.2 C137.2 C138.2 C139.2 C146.2 C148.2 C272.2 C273.1 C274.1 C275.2 C276.2 C279.2 C281.2 C283.2 C285.2 C287.2 C295.2 C298.2 C299.2 C301.2 C302.2 C311.2 C317.2 C318.2 C333.2 C337.2 C351.2 C363.2 C365.2 C401.1 C402.1 C403.2 C404.2 C453.2 C454.2 C456.2 C457.2 J1.2(GND1) J1.3(GND2) J4.1 J4.7 J4.8 J4.13 J4.19 J4.20 J4.25 J4.31 J4.32 J4.37 J4.43 J4.44 J4.49 J4.55 J4.61 J4.67 J4.68 J4.73 J4.79 J4.80 J4.87 J4.92 J4.97 J5.9 J5.10 J5.11 J5.12 J5.13 J5.14 J5.15 J5.16 J5.17 J5.18 J5.19 J5.20 J5.47 J5.48 J5.60 J5.61 J5.72 J5.75 J5.84 J5.89 J6.2 J7.3 J7.6 J7.7 J7.16 J7.17 R215.2 TP44.1(Pin1) TP45.1(Pin1) TP46.1(Pin1) TP47.1(Pin1) U4.A6(VSS1) U4.C4(VSSQ1) U4.E7(VSS2) U4.G5(VSS3) U4.H10(VSS4) U4.J5(VSS5) U4.K8(VSS6) U4.N2(VSSQ2) U4.N5(VSSQ3) U4.P4(VSSQ4) U4.P6(VSSQ5) U5.4(VSS) U5.9(EP) U7.B2(GND) U8.5(AGND) U8.43(BUCK_AGND) U8.57(EPAD) U9.1(GND1) U9.3(GND2) U9.20(GND3) U9.31(GND4) U9.33(GND5) U9.36(GND6) ; also on sheet 5 6 7 8 9
VDD_ARM_0V9: C275.1 C285.1 L5.2 R191.2 R192.1 TP22.1(TP) ; also on sheet 5
VDD_PHY_1V2: C351.1 TP31.1(TP) U8.1(LDO4) ; also on sheet 5
VDD_SNVS_0V8: C337.1 TP29.1(TP) U8.2(LDO2) ; also on sheet 5 8
VDD_SOC&DRAM&PU_0V9: C283.1 C287.1 L6.2 R193.1 R194.2 TP23.1(TP) ; also on sheet 5
VDDA_1V8: C363.1 TP32.1(TP) U8.54(LDO3) ; also on sheet 5
VIN_LDO_CAP: C122.1 L1.2 U9.23(VIN_LDO)
VINT: C274.2 U8.4(VINT)
32K_CLKIN: R115.2 U9.24(SUSCLK_IN(32KHz))
ANT_IN0: C455.1 C456.1 U9.2(WL_BT_ANT)
BOOT_MODE0: J4.98 ; also on sheet 1 8
BOOT_MODE1: J4.100 ; also on sheet 1 8
BOOT_MODE2: J4.60 ; also on sheet 1 8
BOOT_MODE3: J4.56 ; also on sheet 1 8
BT_CTS_RES: R205.1 U9.44(~{UART_CTS})
BT_RTS_RES: R208.1 U9.41(~{UART_RTS})
BT_RXD_RES: R206.1 U9.43(UART_RXD)
BT_TXD_RES: R207.1 U9.42(UART_TXD)
BT_WAKE_DEV: U9.6(HOST_WAKE_BT) ; also on sheet 7
BT_WAKE_HOST: U9.7(BT_WAKE_HOST) ; also on sheet 7
CLK_32K_OUT: U8.7(CLK_32K_OUT) ; also on sheet 8
CLKIN1: J4.94 ; also on sheet 8
CLKIN2: J4.96 ; also on sheet 8
CLKOUT1: J4.64 ; also on sheet 8
CLKOUT2: J4.66 ; also on sheet 8
CSI_CKN: J4.45 ; also on sheet 9
CSI_CKP: J4.47 ; also on sheet 9
CSI_DN0: J4.33 ; also on sheet 9
CSI_DN1: J4.39 ; also on sheet 9
CSI_DN2: J4.51 ; also on sheet 9
CSI_DN3: J4.57 ; also on sheet 9
CSI_DP0: J4.35 ; also on sheet 9
CSI_DP1: J4.41 ; also on sheet 9
CSI_DP2: J4.53 ; also on sheet 9
CSI_DP3: J4.59 ; also on sheet 9
DSI_CKN: J4.15 ; also on sheet 9
DSI_CKP: J4.17 ; also on sheet 9
DSI_DN0: J4.3 ; also on sheet 9
DSI_DN1: J4.9 ; also on sheet 9
DSI_DN2: J4.21 ; also on sheet 9
DSI_DN3: J4.27 ; also on sheet 9
DSI_DP0: J4.5 ; also on sheet 9
DSI_DP1: J4.11 ; also on sheet 9
DSI_DP2: J4.23 ; also on sheet 9
DSI_DP3: J4.29 ; also on sheet 9
ECSPI2_MISO: J4.16 ; also on sheet 7
ECSPI2_MOSI: J4.18 ; also on sheet 7
ECSPI2_SCLK: J4.14 ; also on sheet 7
ECSPI2_SS0: J4.12 ; also on sheet 7
eMMC_VDDIM: C136.1 C137.1 U4.C2(VDDI)
ENET_MDC: J7.18 ; also on sheet 7
ENET_MDIO: J7.20 ; also on sheet 7
ENET_RD0: J7.8 ; also on sheet 7
ENET_RD1: J7.10 ; also on sheet 7
ENET_RD2: J7.12 ; also on sheet 7
ENET_RD3: J7.14 ; also on sheet 7
ENET_RX_CTL: J7.2 ; also on sheet 7
ENET_RXC: J7.4 ; also on sheet 7
ENET_TD0: J7.9 ; also on sheet 7
ENET_TD1: J7.11 ; also on sheet 7
ENET_TD2: J7.13 ; also on sheet 7
ENET_TD3: J7.15 ; also on sheet 7
ENET_TX_CTL: J7.1 ; also on sheet 7
ENET_TXC: J7.5 ; also on sheet 7
GPIO1_IO01: J5.64 ; also on sheet 7
GPIO1_IO05: J5.62 ; also on sheet 7
GPIO1_IO06: J5.58 ; also on sheet 7
GPIO1_IO07: J5.56 ; also on sheet 7
GPIO1_IO08: J5.54 ; also on sheet 7
GPIO1_IO09: J5.52 ; also on sheet 7
GPIO1_IO10: J5.50 ; also on sheet 7
GPIO1_IO11: J5.46 ; also on sheet 7
GPIO1_IO12: J5.44 ; also on sheet 7
GPIO1_IO13: J5.42 ; also on sheet 7
GPIO1_IO14: J5.40 ; also on sheet 7
GPIO1_IO15: J5.38 ; also on sheet 7
I2C1_SCL: R48.1 ; also on sheet 7
I2C1_SDA: R54.1 ; also on sheet 7
I2C2_SCL: J4.22 ; also on sheet 7
I2C2_SDA: J4.24 ; also on sheet 7
I2C3_SCL: J4.26 ; also on sheet 7
I2C3_SDA: J4.28 ; also on sheet 7
I2C4_SCL: J4.30 ; also on sheet 7
I2C4_SDA: J4.34 ; also on sheet 7
JTAG_TCK: J4.62 ; also on sheet 8
JTAG_TDI: J4.54 ; also on sheet 8
JTAG_TDO: J4.52 ; also on sheet 8
JTAG_TMS: J4.58 ; also on sheet 8
LX1: L6.1 U8.36(LX1_1) U8.37(LX1_2)
LX2: L5.1 U8.45(LX2_1) U8.46(LX2_2)
LX4: L11.1 U8.19(LX4_1) U8.20(LX4_2)
LX5: L13.1 U8.15(LX5)
LX6: L15.1 U8.50(LX6_1) U8.51(LX6_2)
M.2_32K_OUT: J5.37 R116.2
NVCC_1V8: C130.1 C131.1 C132.1 C133.1 C138.1 C139.1 C146.1 C317.1 C404.1 J5.22 J5.24 J5.26 J5.28 J5.30 J5.32 J5.34 J5.36 L13.2 R37.1 R61.2 R106.1 R117.1 R118.1 R196.1 R197.1 TP26.1(TP) U4.C6(VCCQ1) U4.M4(VCCQ2) U4.N4(VCCQ3) U4.P3(VCCQ4) U4.P5(VCCQ5) U5.8(VCC) U7.A1(VIN) U8.14(BUCK5FB) ; also on sheet 1 5 6 7
NVCC_3V3: C121.1 C127.1 C128.1 C129.1 C276.1 C311.1 C403.1 J5.21 J5.23 J5.25 J5.27 J5.29 J5.31 J5.33 J5.35 L11.2 R137.1 R153.1 R200.1 R201.1 TP25.1(TP) U4.E6(VCC1) U4.F5(VCC2) U4.J10(VCC3) U4.K9(VCC4) U8.21(BUCK4FB) U8.22(SWIN) U9.9(VBAT) ; also on sheet 5 7
NVCC_DRAM_1V1: C318.1 L15.2 TP27.1(TP) U8.52(BUCK6FB) ; also on sheet 5 6
NVCC_ENET: C2.1 J7.19 ; also on sheet 5
NVCC_SD2: C365.1 TP33.1(TP) U8.55(LDO5) ; also on sheet 5 7
NVCC_SNVS_1V8: C333.1 TP28.1(TP) U8.3(LDO1) ; also on sheet 5 8
ONOFF: J4.46 ; also on sheet 8
PDM_CLK: J5.65 ; also on sheet 7
PDM_DATA0: J5.67 ; also on sheet 7
PDM_DATA1: J5.69 ; also on sheet 7
PDM_DATA2: J5.71 ; also on sheet 7
PDM_DATA3: J5.73 ; also on sheet 7
PMIC_nINT: R61.1 U8.13(IRQ_B) ; also on sheet 7
PMIC_ON_REQ: J4.48 R51.1 ; also on sheet 8
PMIC_STBY_REQ: R52.1 ; also on sheet 8
POR_B: J4.50 R114.2 ; also on sheet 8
QSPIA_DATA0: TP16.1(TP) U5.5(DQ0) ; also on sheet 7
QSPIA_DATA1: U5.2(DQ1) ; also on sheet 7
QSPIA_DATA2: U5.3(~{W}/DQ2) ; also on sheet 7
QSPIA_DATA3: U5.7(~{HOLD}/DQ3) ; also on sheet 7
QSPIA_nSS0: R37.2 U5.1(~{S}) ; also on sheet 7
QSPIA_SCLK: TP17.1(TP) U5.6(C) ; also on sheet 7
R_SNSP1: R193.2 R194.1 U8.38(R_SNSP1)
R_SNSP2: R191.1 R192.2 U8.44(R_SNSP2)
REF_CLK_32K: R115.1 R116.1 ; also on sheet 7
REG_PD_B: U9.12(PDn) ; also on sheet 7
RF_ANT0: C455.2 C457.1 J1.1(CTR)
RTC_RESET_B: R111.2 ; also on sheet 8
SAI2_MCLK: J5.66 ; also on sheet 7
SAI2_RXC: J5.79 ; also on sheet 7
SAI2_RXD: R132.2 ; also on sheet 7
SAI2_RXD_RES: R132.1 U9.25(BT_PCM_OUT)
SAI2_RXFS: J5.68 ; also on sheet 7
SAI2_TXC: R131.2 R198.1 ; also on sheet 7
SAI2_TXC_1P8: R196.2 R198.2 U8.27(SCLL)
SAI2_TXC_3P3: J5.87 R203.1
SAI2_TXC_RES: R131.1 U9.26(BT_PCM_CLK)
SAI2_TXD: R130.2 R199.1 ; also on sheet 7
SAI2_TXD_1P8: R197.2 R199.2 U8.26(SDAL)
SAI2_TXD_3P3: J5.91 R202.1
SAI2_TXD_RES: R130.1 U9.27(BT_PCM_IN)
SAI2_TXFS: R129.2 ; also on sheet 7
SAI2_TXFS_RES: R129.1 U9.28(BT_PCM_SYNC)
SAI3_MCLK: J5.41 ; also on sheet 7
SAI3_RXC: J5.53 ; also on sheet 7
SAI3_RXD: J5.55 ; also on sheet 7
SAI3_RXFS: J5.51 ; also on sheet 7
SAI3_TXC: J5.45 ; also on sheet 7
SAI3_TXD: J5.49 ; also on sheet 7
SAI3_TXFS: J5.43 ; also on sheet 7
SAI5_MCLK: J5.77 ; also on sheet 7
SAI5_RXFS: J5.70 ; also on sheet 7
SD1_CLK: R214.1 TP66.1(Pin1) ; also on sheet 7
SD1_CLK_R: R214.2 U9.17(SDIO_CLK)
SD1_CMD: R213.1 TP67.1(Pin1) ; also on sheet 7
SD1_CMD_R: R213.2 U9.16(SDIO_CMD)
SD1_DATA0: R209.1 TP24.1(Pin1) ; also on sheet 7
SD1_DATA0_R: R209.2 U9.18(SDIO_DATA0)
SD1_DATA1: R210.1 ; also on sheet 7
SD1_DATA1_R: R210.2 U9.19(SDIO_DATA1)
SD1_DATA2: R211.1 ; also on sheet 7
SD1_DATA2_R: R211.2 U9.14(SDIO_DATA2)
SD1_DATA3: R212.1 ; also on sheet 7
SD1_DATA3_R: R212.2 U9.15(SDIO_DATA3)
SD1_STROBE: J4.70 ; also on sheet 7
SD2_CLK: J4.76 ; also on sheet 7
SD2_CMD: J4.78 ; also on sheet 7
SD2_DATA0: J4.84 ; also on sheet 7
SD2_DATA1: J4.82 ; also on sheet 7
SD2_DATA2: J4.72 ; also on sheet 7
SD2_DATA3: J4.74 ; also on sheet 7
SD2_nCD: J4.88 ; also on sheet 7
SD2_nRST: J4.90 ; also on sheet 7
SD2_VSEL: U8.29(SD_VSEL) ; also on sheet 7
SD2_WP: J4.86 ; also on sheet 7
SD3_CLK: TP34.1(Pin1) U4.M6(CLK) ; also on sheet 7
SD3_CMD: R118.2 TP35.1(Pin1) U4.M5(CMD) ; also on sheet 7
SD3_DATA0: R117.2 TP36.1(Pin1) U4.A3(DAT0) ; also on sheet 7
SD3_DATA1: U4.A4(DAT1) ; also on sheet 7
SD3_DATA2: U4.A5(DAT2) ; also on sheet 7
SD3_DATA3: U4.B2(DAT3) ; also on sheet 7
SD3_DATA4: U4.B3(DAT4) ; also on sheet 7
SD3_DATA5: U4.B4(DAT5) ; also on sheet 7
SD3_DATA6: U4.B5(DAT6) ; also on sheet 7
SD3_DATA7: U4.B6(DAT7) ; also on sheet 7
SD3_STROBE: TP40.1(Pin1) U4.H5(RCLK) ; also on sheet 7
SPDIF_EXT_CLK: J5.63 ; also on sheet 7
SPDIF_RX: J5.59 ; also on sheet 7
SPDIF_TX: J5.57 ; also on sheet 7
SW_EN: R137.2 U8.12(SW_EN)
SWOUT_3V3: C273.2 TP68.1(TP) U8.23(SWOUT)
SYS_nRST: J5.39 R127.1
UART1_CTS: R205.2 ; also on sheet 7
UART1_RTS: R208.2 ; also on sheet 7
UART1_RXD: R207.2 ; also on sheet 7
UART1_TXD: R206.2 ; also on sheet 7
UART2_RXD: J4.36 ; also on sheet 7
UART2_TXD: J4.38 ; also on sheet 7
UART3_CTS: J4.10 ; also on sheet 7
UART3_RTS: J4.2 ; also on sheet 7
UART3_RXD: J4.4 ; also on sheet 7
UART3_TXD: J4.6 ; also on sheet 7
UART4_RXD: J4.40 ; also on sheet 7
UART4_TXD: J4.42 ; also on sheet 7
USB1_DN: J4.83 ; also on sheet 9
USB1_DP: J4.85 ; also on sheet 9
USB1_ID: J4.89 ; also on sheet 9
USB1_VBUS: J4.81 ; also on sheet 9
VSYS_5V: C13.1 C272.1 C279.1 C281.1 C295.1 C301.1 C302.1 C401.2 C402.2 C453.1 J5.1 J5.2 J5.3 J5.4 J5.5 J5.6 J5.7 J5.8 J6.1 R195.2 TP51.1(TP) U8.16(INB45_1) U8.17(INB45_2) U8.18(INB45_3) U8.33(INB13_1) U8.34(INB13_2) U8.35(INB13_3) U8.47(INB26_1) U8.48(INB26_2) U8.49(INB26_3) U8.53(VSYS) U8.56(INL1)
WDOG_B: R55.1 TP53.1(TP) ; also on sheet 7
WIFI_1V8: C454.1 TP13.1(Pin1) U7.A2(VOUT) U9.22(VDDIO)
WL_WAKE_DEV: U9.39(HOST_WL_WAKE) ; also on sheet 7
WL_WAKE_HOST: U9.13(WL_HOST_WAKE) ; also on sheet 7
XIN_32K: C298.1 QZ2.2 U8.10(XTAL_IN)
XOUT_32K: C299.1 QZ2.1 U8.11(XTAL_OUT)
N106740715: R114.1 U8.9(POR_B)
N106743010: R55.2 R106.2 U8.28(WDOG_B)
N106743238: R51.2 U8.39(PMIC_ON_REQ)
N106743319: R52.2 U8.40(PMIC_STBY_REQ)
N106743947: R111.1 U8.6(RTC_RESET_B)
N108008688: R127.2 U8.8(PMIC_RST_B)
N109411711: R195.1 U8.30(R_SNSP3_CFG)
N109413799: R48.2 U8.41(SCL)
N109414410: R54.2 U8.42(SDA)
N109458619: TP18.1(Pin1) U4.K5(~{RST})
N109540553: R201.2 R203.2 U8.25(SCLH)
N109540574: R200.2 R202.2 U8.24(SDAH)
N109658934: L1.1 U9.21(VIN_LDO_OUT)
N109688415: C148.1 R153.2 R215.1 TP12.1(Pin1) U7.B1(EN)

Not connected (* = marked no-connect by the designer): J4 63* 65* 69* 71* 75* 77* 91* 93* 95* 99*; J5 74* 76* 78* 80* 81* 82* 83* 85* 86* 88* 90* 92* 93* 94* 95* 96* 97* 98* 99* 100*; U4 A1(NC)* A2(NC)* A7(NC)* A8(NC)* A9(NC)* A10(NC)* A11(NC)* A12(NC)* A13(NC)* A14(NC)* B1(NC)* B7(NC)* B8(NC)* B9(NC)* B10(NC)* B11(NC)* B12(NC)* B13(NC)* B14(NC)* C1(NC)* C3(NC)* C5(NC)* C7(NC)* C8(NC)* C9(NC)* C10(NC)* C11(NC)* C12(NC)* C13(NC)* C14(NC)* D1(NC)* D2(NC)* D3(NC)* D4(NC)* D12(NC)* D13(NC)* D14(NC)* E1(NC)* E2(NC)* E3(NC)* E5(NC)* E8(NC)* E9(VSF1)* E10(VSF2)* E12(NC)* E13(NC)* E14(NC)* F1(NC)* F2(NC)* F3(NC)* F10(VSF3)* F12(NC)* F13(NC)* F14(NC)* G1(NC)* G2(NC)* G3(NC)* G10(NC)* G12(NC)* G13(NC)* G14(NC)* H1(NC)* H2(NC)* H3(NC)* H12(NC)* H13(NC)* H14(NC)* J1(NC)* J2(NC)* J3(NC)* J12(NC)* J13(NC)* J14(NC)* K1(NC)* K2(NC)* K3(NC)* K6(NC)* K7(NC)* K10(VSF4)* K12(NC)* K13(NC)* K14(NC)* L1(NC)* L2(NC)* L3(NC)* L12(NC)* L13(NC)* L14(NC)* M1(NC)* M2(NC)* M3(NC)* M7(NC)* M8(NC)* M9(NC)* M10(NC)* M11(NC)* M12(NC)* M13(NC)* M14(NC)* N1(NC)* N3(NC)* N6(NC)* N7(NC)* N8(NC)* N9(NC)* N10(NC)* N11(NC)* N12(NC)* N13(NC)* N14(NC)* P1(NC)* P2(NC)* P7(NC)* P8(NC)* P9(NC)* P10(NC)* P11(NC)* P12(NC)* P13(NC)* P14(NC)*; U8 31(LX3_1)* 32(LX3_2)*; U9 4(NC1)* 5(NC2)* 8(NC3)* 10(XTAL_IN)* 11(XTAL_OUT)* 29(NC4)* 30(NC5)* 32(NC6)* 34(NC7)* 35(NC8)* 37(NC9)* 38(NC10)* 40(NC12)* 45(NC13)* 46(NC14)* 47(NC15)*

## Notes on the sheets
sheet 10
- 2.4G/5G WIFI/BT Module
- Power Sequence
- 3.3V
- VBAT
- 1.8V
- VDDIO/PDn
- VIO Must be powered after VBAT
- i
- o
- o
- o
- i
- i
- i
- o
- o
- # 1.8V(Fixed)
- Antenna 2.4G/5G
- Layout:
- The 38.4MHz crystal has been embedded into module
- Matching
  Circuit
- Route the Antenna trace as 50 ohm.
- 88W8987 Based
- Note:
- 1. Time from EN reaches 1.2V to VOUT starts ramping is 40us typical
  2. RC delay adder is used to make sure WIFI_1V8 powers up after VDD_3V3
sheet 11
- B2B Connector for CPU Board
- Header
- Receptacle
- A53 Debug
- M7 Debug
- Receptacle
- When using M.2 WIFI Module, remove R115, populate R116!
sheet 12
- SYS PMIC
- 1.8V 10mA
- 0.85/0.95/1.0V 3A
- 0.8V 10mA
- Sense from processor power pins
- 0.85/0.95V 3A
- 1.8V 300mA
- 1.2V 200mA
- 3.3V/1.8V 150mA
- 3.3V 3A
- 1.8V 2A
- GND Testpoints
- Backup PWR Supply
- 1.1V 2A
- i.MX8M Nano LPDDR4 EVK Power Sequence
- SEQ
- PWR/Signal
- REG
- MIN
- TYP
- MAX
- Max Current(mA)
- 1
  2
  3
  4
  5
  6
  6
  7
  8
  9
  9
  10
  11
- NVCC_SNVS_1V8
  VDD_SNVS_0V8
  RTC_RESET_B
  CLK_32K_OUT
  VDD_SOC&DRAM&PU_0V9
  VDD_ARM_0V9
  VDDA_1V8
  VDD_1V8/NVCC_1V8
  NVCC_DRAM_1V1
  VDD_3V3/NVCC_3V3
  NVCC_SD2
  POR_B
  VDD_PHY_1V2
- LDO1
  LDO2
  RTC_RESET_B
  RTC_CLK
  BUCK1
  BUCK2
  LDO3
  BUCK5
  BUCK6
  BUCK4
  LDO5
  POR_B
  LDO4
- 1.62
  0.76
  --
  --
  0.805/0.9
  0.805/0.9/0.95
  1.71
  1.65
  1.06
  3
  3.0/1.65
  --
  1.14
- 1.8
  0.8
  --
  --
  0.85/0.95
  0.85/0.95/1.0
  1.8
  1.8
  1.1
  3.3
  3.3/1.8
  --
  1.2
- 1.98
  0.9
  --
  --
  0.95/1.0
  0.95/1.0/1.05
  1.89
  1.95
  1.14
  3.6
  3.6/1.95
  --
  1.26
- 10
  10
  --
  --
  3000
  3000
  300
  2000
  2000
  3000
  150
  --
  200
- # System Reset Button
- PU
- # CPU WDOG_B Reset
- OD
- OD
- When using Base Board, DNP R198/R199/R200/R201, polulate R130/R131
  When using Audio board V2, polulate R198/R199/R200/R201,
  DNP R130/R131.
- Note:
- 1. WDOG_B is used as Cold Reset, external pull up is needed. On EVK, R106 is not necessary, since WDOG_B/GPIO1_IO02 of CPU has internal pull up.
- 2. PMIC_nINT is open drain output, external pull up is needed. On EVK, R61 is not necessary, since PMIC_nINT/GPIO1_IO03 of CPU has internal pull up.
- 3. AGND/BUCK_AGND should be connected to ground plane through Via. Do not short to EP directly on top layer
sheet 13
- Storage
- eMMC
- # 1.8V(Fixed)
- 32GB
- QSPI Flash
- 32MB
